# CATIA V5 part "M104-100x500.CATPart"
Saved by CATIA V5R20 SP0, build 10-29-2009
Part number: M104-100x500
Source: Unknown
Bounding box of the stored display mesh (mm): x -49.986 to 49.986, y -49.986 to 49.986, z 0 to 500
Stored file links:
  C:\Users\Utente\Desktop\IO LAVORO\3D X SITO CF\X SITO\M104\M104-100x500.CATPart
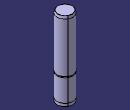
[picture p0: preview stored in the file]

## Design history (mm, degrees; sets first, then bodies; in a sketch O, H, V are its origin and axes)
Body1 (main body)
  Solid1 "PartBody": solid without history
